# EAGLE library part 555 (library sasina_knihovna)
Casovac 555.
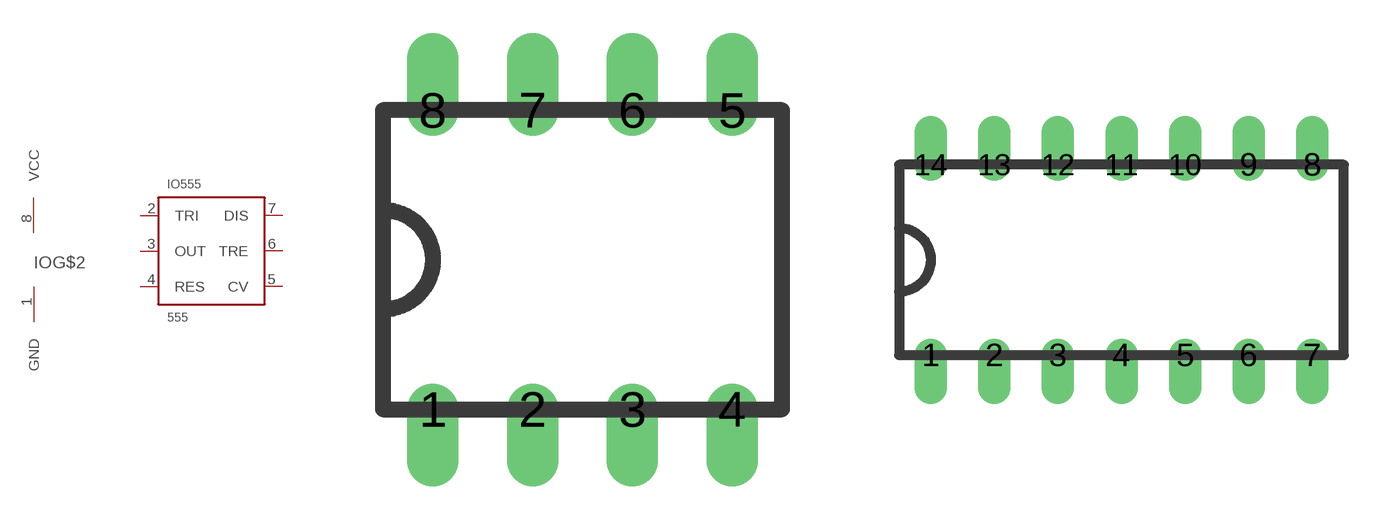
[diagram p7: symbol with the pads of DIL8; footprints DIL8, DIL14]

Designator prefix IO; gates 555=555 G$2=NAPAJENI

## 555D  [DIL8]
1  G$2:GND  pwr
2  555:TRI  in
3  555:OUT  out
4  555:RES  in
5  555:CV  pas
6  555:TRE  in
7  555:DIS  out
8  G$2:VCC  pwr

## 555N  [DIL8]
Pads as for DIL8

## 555FE  [DIL8]
Pads as for DIL8

## 555F  [DIL14]
1  G$2:GND  pwr
3  555:TRI  in
4  555:OUT  out
6  555:RES  in
8  555:CV  pas
10  555:TRE  in
12  555:DIS  out
14  G$2:VCC  pwr

## Footprint DIL8 (pad centres in mm)
drill 0.8 offset: 1 0,-1.27; 2 2.54,-1.27; 3 5.08,-1.27; 4 7.62,-1.27; 5 7.62,6.35; 6 5.08,6.35; 7 2.54,6.35; 8 0,6.35

## Footprint DIL14 (pad centres in mm)
drill 0.8 offset: 1 0,-1.27; 2 2.54,-1.27; 3 5.08,-1.27; 4 7.62,-1.27; 5 10.16,-1.27; 6 12.7,-1.27; 7 15.24,-1.27; 8 15.24,6.35; 9 12.7,6.35; 10 10.16,6.35; 11 7.62,6.35; 12 5.08,6.35; 13 2.54,6.35; 14 0,6.35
